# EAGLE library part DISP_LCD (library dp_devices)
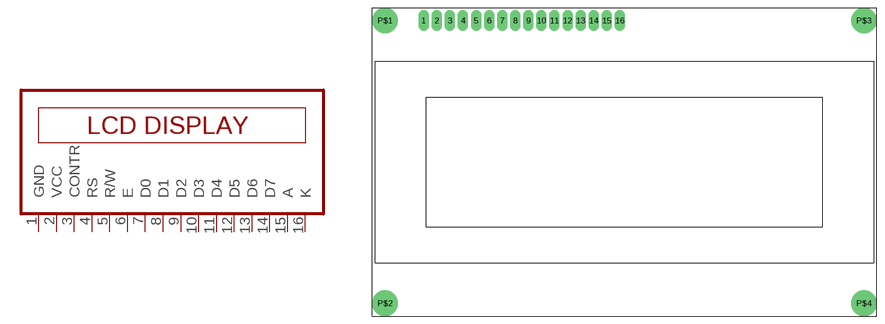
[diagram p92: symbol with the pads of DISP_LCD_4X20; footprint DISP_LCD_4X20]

Designator prefix LCD

## DISP_LCD-4X20  [DISP_LCD_4X20]
1  GND  sup
2  VCC  sup
3  CONTR  in
4  RS  in
5  R/W  in
6  E  in
7  D0  in
8  D1  in
9  D2  in
10  D3  in
11  D4  in
12  D5  in
13  D6  in
14  D7  in
15  A  sup
16  K  sup

## Footprint DISP_LCD_4X20 (pad centres in mm)
drill 1 pad 2 long: 1 -39,27.5; 2 -36.46,27.5; 3 -33.92,27.5; 4 -31.38,27.5; 5 -28.84,27.5; 6 -26.3,27.5; 7 -23.76,27.5; 8 -21.22,27.5; 9 -18.68,27.5; 10 -16.14,27.5; 11 -13.6,27.5; 12 -11.06,27.5; 13 -8.52,27.5; 14 -5.98,27.5; 15 -3.44,27.5; 16 -0.9,27.5
drill 2.5 pad 5 round: P$1 -46.5,27.5; P$2 -46.5,-27.5; P$3 46.5,27.5; P$4 46.5,-27.5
